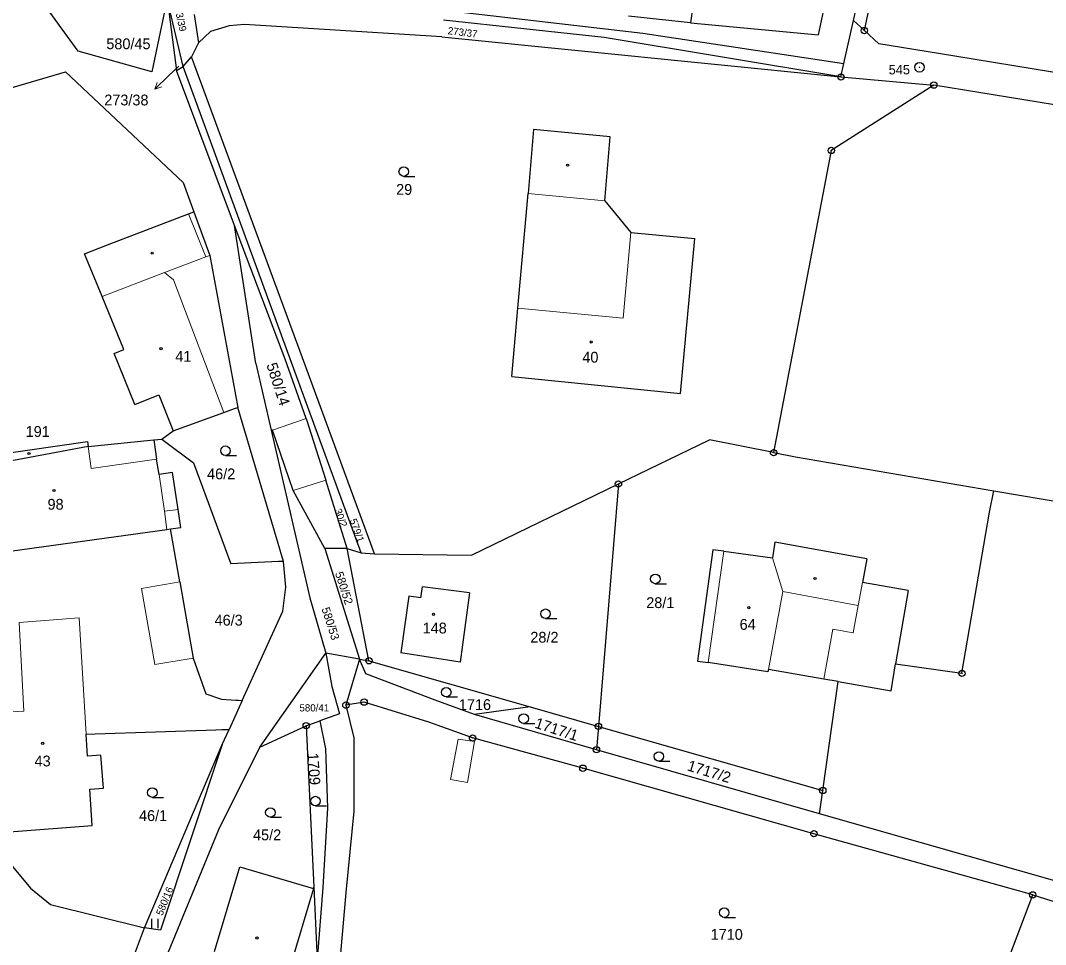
# Model space of a CAD drawing. Extents: x -601131 to -597152, y -1058536 to -1055911.
# Drawn here: x -599420.5 to -599259.4, y -1057423.7 to -1057278.4 of the extents above; entities that cross this region are included whole.
import ezdxf
from ezdxf.enums import TextEntityAlignment as Align

# ---------------------------------------------------------------- set-up
doc = ezdxf.new("R2010")
doc.units = 0
doc.header["$LTSCALE"] = 0.68
for name, color, linetype, lineweight in [('1', 7, 'Continuous', 25), ('3', 7, 'Continuous', 25), ('4', 7, 'Continuous', 13), ('5', 7, 'Continuous', 25), ('7', 7, 'Continuous', 13), ('8', 7, 'Continuous', 25)]:
    doc.layers.add(name, color=color, linetype=linetype, lineweight=lineweight)
doc.layers.add('2', color=7, linetype='Continuous')

msp = doc.modelspace()

# ---------------------------------------------------------------- linework, layer by layer
at = {"layer": '1'}
for p, q in [((-599289.57, -1057278.37), (-599276.24, -1057217.2)), ((-599309.65, -1057241.5), (-599315.21, -1057278.73)), ((-599295.06, -1057280.63), (-599287.53, -1057245.47)), ((-599287.86, -1057279.94), (-599281.16, -1057249.18)), ((-599411.44, -1057283.19), (-599419.47, -1057272.04)), ((-599397.46, -1057274.9), (-599399.88, -1057286.45)), ((-599394.93, -1057285.61), (-599397.46, -1057274.9)), ((-599397.46, -1057274.9), (-599395.98, -1057286.23)), ((-599393.21, -1057277.43), (-599392.54, -1057281.88)), ((-599353.84, -1057276.72), (-599322.66, -1057280.34)), ((-599385.29, -1057278.99), (-599387.72, -1057279.22)), ((-599354.25, -1057280.95), (-599385.29, -1057278.99)), ((-599328.78, -1057281.02), (-599353.99, -1057278.29)), ((-599315.21, -1057278.73), (-599324.94, -1057277.69)), ((-599315.21, -1057278.73), (-599295.06, -1057280.63)), ((-599291.08, -1057285.15), (-599289.57, -1057278.37)), ((-599287.86, -1057279.94), (-599289.57, -1057278.37)), ((-599390.63, -1057280.08), (-599392.54, -1057281.88)), ((-599387.72, -1057279.22), (-599390.63, -1057280.08)), ((-599322.66, -1057280.34), (-599291.08, -1057285.15)), ((-599285.6, -1057282.02), (-599287.86, -1057279.94)), ((-599392.54, -1057281.88), (-599393.64, -1057284.09)), ((-599354.25, -1057280.95), (-599291.54, -1057287.24)), ((-599291.54, -1057287.24), (-599328.78, -1057281.02)), ((-599276.23, -1057283.57), (-599285.6, -1057282.02)), ((-599399.88, -1057286.45), (-599411.44, -1057283.19)), ((-599251, -1057287.69), (-599276.23, -1057283.57)), ((-599395.98, -1057286.23), (-599394.93, -1057285.61)), ((-599394.93, -1057285.61), (-599393.64, -1057284.09)), ((-599366.95, -1057362.1), (-599394.93, -1057285.61)), ((-599375.82, -1057332.4), (-599393.64, -1057284.09)), ((-599291.54, -1057287.24), (-599291.08, -1057285.15)), ((-599425.53, -1057290.01), (-599413.41, -1057286.42)), ((-599413.41, -1057286.42), (-599394.93, -1057303.86)), ((-599386.84, -1057310.62), (-599395.98, -1057286.23)), ((-599291.54, -1057287.24), (-599276.95, -1057288.52)), ((-599276.95, -1057288.52), (-599293.06, -1057298.8)), ((-599241.43, -1057294.32), (-599276.95, -1057288.52)), ((-599339.85, -1057295.49), (-599340.72, -1057305.59)), ((-599327.81, -1057296.68), (-599339.85, -1057295.49)), ((-599328.67, -1057306.73), (-599327.81, -1057296.68)), ((-599293.06, -1057298.8), (-599302.13, -1057346.32)), ((-599394.93, -1057303.86), (-599393.26, -1057308.44)), ((-599342.34, -1057323.58), (-599340.72, -1057305.59)), ((-599328.67, -1057306.73), (-599324.55, -1057311.68)), ((-599406.81, -1057313.66), (-599394.07, -1057308.75)), ((-599394.07, -1057308.75), (-599393.26, -1057308.44)), ((-599393.26, -1057308.44), (-599390.76, -1057315.3)), ((-599378.9, -1057331.64), (-599386.84, -1057310.62)), ((-599383.52, -1057332.3), (-599386.84, -1057310.62)), ((-599324.55, -1057311.68), (-599314.52, -1057312.63)), ((-599316.77, -1057337.04), (-599314.52, -1057312.63)), ((-599410.42, -1057315.05), (-599406.81, -1057313.66)), ((-599407.67, -1057321.76), (-599410.42, -1057315.05)), ((-599390.76, -1057315.3), (-599386.33, -1057339.21)), ((-599404.27, -1057330.12), (-599407.67, -1057321.76)), ((-599343.29, -1057334.36), (-599342.34, -1057323.58)), ((-599405.78, -1057330.74), (-599404.27, -1057330.12)), ((-599402.52, -1057338.76), (-599405.78, -1057330.74)), ((-599383.52, -1057332.3), (-599381.1, -1057342.81)), ((-599375.62, -1057340.95), (-599378.9, -1057331.64)), ((-599364.88, -1057362.22), (-599375.82, -1057332.4)), ((-599343.29, -1057334.36), (-599316.77, -1057337.04)), ((-599402.52, -1057338.76), (-599398.77, -1057337.24)), ((-599398.77, -1057337.24), (-599396.48, -1057342.88)), ((-599396.48, -1057342.88), (-599388.55, -1057340.01)), ((-599388.55, -1057340.01), (-599386.87, -1057339.39)), ((-599386.87, -1057339.39), (-599386.33, -1057339.21)), ((-599379.14, -1057363.42), (-599386.33, -1057339.21)), ((-599375.62, -1057340.95), (-599372.49, -1057350.63)), ((-599398.26, -1057344.19), (-599396.48, -1057342.88)), ((-599380.9, -1057342.78), (-599381.1, -1057342.81)), ((-599381.1, -1057342.81), (-599375.04, -1057369.18)), ((-599377.65, -1057352.25), (-599380.9, -1057342.78)), ((-599425.85, -1057346.84), (-599409.99, -1057344.56)), ((-599409.99, -1057344.56), (-599409.88, -1057345.35)), ((-599409.88, -1057345.35), (-599399.55, -1057344.32)), ((-599399.55, -1057344.32), (-599398.26, -1057344.19)), ((-599399.55, -1057344.32), (-599399.11, -1057347.35)), ((-599398.26, -1057344.19), (-599393.33, -1057347.95)), ((-599326.52, -1057351.25), (-599312.23, -1057344.33)), ((-599302.13, -1057346.32), (-599312.23, -1057344.33)), ((-599409.88, -1057345.35), (-599425.64, -1057348.31)), ((-599302.13, -1057346.32), (-599298.7, -1057346.97)), ((-599398.71, -1057349.77), (-599399.11, -1057347.35)), ((-599393.33, -1057347.95), (-599387.43, -1057363.83)), ((-599298.7, -1057346.97), (-599267.5, -1057352.34)), ((-599396.59, -1057349.42), (-599398.71, -1057349.77)), ((-599395.7, -1057355.26), (-599396.59, -1057349.42)), ((-599369.18, -1057361.4), (-599372.49, -1057350.63)), ((-599349.59, -1057362.45), (-599326.52, -1057351.25)), ((-599326.52, -1057351.25), (-599329.66, -1057389.37)), ((-599372.68, -1057361.4), (-599377.65, -1057352.25)), ((-599268.21, -1057355.67), (-599267.5, -1057352.34)), ((-599267.5, -1057352.34), (-599196.38, -1057364.38)), ((-599395.29, -1057358.08), (-599395.7, -1057355.26)), ((-599272.52, -1057381.02), (-599268.21, -1057355.67)), ((-599396.94, -1057358.31), (-599395.29, -1057358.08)), ((-599423.64, -1057362.04), (-599397.5, -1057358.39)), ((-599397.5, -1057358.39), (-599396.94, -1057358.31)), ((-599395.47, -1057366.62), (-599396.94, -1057358.31)), ((-599301.96, -1057360.38), (-599302.3, -1057362.89)), ((-599287.49, -1057363.01), (-599301.96, -1057360.38)), ((-599369.18, -1057361.4), (-599372.68, -1057361.4)), ((-599365.73, -1057379.05), (-599369.18, -1057361.4)), ((-599369.18, -1057361.4), (-599366.95, -1057362.1)), ((-599366.95, -1057362.1), (-599364.88, -1057362.22)), ((-599364.88, -1057362.22), (-599349.59, -1057362.45)), ((-599311.68, -1057361.6), (-599314.09, -1057379.09)), ((-599309.95, -1057361.84), (-599311.68, -1057361.6)), ((-599309.95, -1057361.84), (-599302.3, -1057362.89)), ((-599379.93, -1057363.46), (-599387.43, -1057363.83)), ((-599379.14, -1057363.42), (-599379.93, -1057363.46)), ((-599378.8, -1057367.46), (-599379.14, -1057363.42)), ((-599287.49, -1057363.01), (-599288.17, -1057366.75)), ((-599395.47, -1057366.62), (-599393.34, -1057378.62)), ((-599379.24, -1057371.27), (-599378.8, -1057367.46)), ((-599357.55, -1057369.13), (-599357.33, -1057367.44)), ((-599349.92, -1057368.39), (-599357.33, -1057367.44)), ((-599280.98, -1057368), (-599288.17, -1057366.75)), ((-599375.04, -1057369.18), (-599372.49, -1057377.88)), ((-599359.48, -1057368.87), (-599360.7, -1057377.83)), ((-599357.55, -1057369.13), (-599359.48, -1057368.87)), ((-599349.92, -1057368.39), (-599351.41, -1057379.27)), ((-599280.98, -1057368), (-599282.95, -1057379.52)), ((-599385.64, -1057385.31), (-599379.24, -1057371.27)), ((-599393.34, -1057378.62), (-599391.38, -1057384.25)), ((-599382.87, -1057392.64), (-599372.49, -1057377.88)), ((-599367.24, -1057378.79), (-599372.49, -1057377.88)), ((-599372.49, -1057377.88), (-599371.54, -1057383.11)), ((-599367.24, -1057378.79), (-599369.35, -1057386.03)), ((-599366.21, -1057381.11), (-599367.24, -1057378.79)), ((-599365.73, -1057379.05), (-599340.38, -1057386.3)), ((-599351.41, -1057379.27), (-599360.7, -1057377.83)), ((-599314.09, -1057379.09), (-599312.39, -1057379.35)), ((-599303.02, -1057380.77), (-599312.39, -1057379.35)), ((-599302.95, -1057380.4), (-599303.02, -1057380.77)), ((-599294.24, -1057381.92), (-599302.95, -1057380.4)), ((-599283.65, -1057383.76), (-599282.95, -1057379.52)), ((-599282.95, -1057379.52), (-599272.52, -1057381.02)), ((-599355.31, -1057385.24), (-599366.21, -1057381.11)), ((-599292, -1057382.32), (-599294.24, -1057381.92)), ((-599371.54, -1057383.11), (-599370.34, -1057387.38)), ((-599294.4, -1057399.45), (-599292, -1057382.32)), ((-599292, -1057382.32), (-599283.65, -1057383.76)), ((-599391.38, -1057384.25), (-599388.93, -1057385.08)), ((-599388.93, -1057385.08), (-599386.67, -1057385.24)), ((-599385.64, -1057385.31), (-599387.7, -1057389.84)), ((-599386.67, -1057385.24), (-599386.25, -1057385.27)), ((-599386.25, -1057385.27), (-599385.64, -1057385.31)), ((-599349.16, -1057387.51), (-599355.31, -1057385.24)), ((-599366.49, -1057385.56), (-599369.35, -1057386.03)), ((-599369.35, -1057386.03), (-599368.11, -1057391.18)), ((-599356.3, -1057388.72), (-599366.49, -1057385.56)), ((-599340.38, -1057386.3), (-599349.16, -1057387.51)), ((-599340.38, -1057386.3), (-599329.66, -1057389.37)), ((-599375.59, -1057389.26), (-599373.46, -1057388.5)), ((-599370.34, -1057387.38), (-599373.46, -1057388.5)), ((-599373.46, -1057388.5), (-599372.57, -1057392.88)), ((-599349.44, -1057391.19), (-599356.3, -1057388.72)), ((-599329.97, -1057393.04), (-599349.16, -1057387.51)), ((-599408.76, -1057390.52), (-599389.82, -1057389.91)), ((-599389.82, -1057389.91), (-599388.82, -1057389.88)), ((-599388.82, -1057389.88), (-599387.7, -1057389.84)), ((-599388.79, -1057392.24), (-599387.7, -1057389.84)), ((-599382.87, -1057392.64), (-599375.59, -1057389.26)), ((-599375.59, -1057389.26), (-599374.41, -1057414.64)), ((-599329.66, -1057389.37), (-599329.97, -1057393.04)), ((-599329.66, -1057389.37), (-599294.4, -1057399.45)), ((-599410.19, -1057390.57), (-599408.76, -1057390.52)), ((-599409.98, -1057394.05), (-599410.19, -1057390.57)), ((-599368.11, -1057391.18), (-599368.13, -1057402.69)), ((-599332.11, -1057395.95), (-599349.44, -1057391.19)), ((-599400.99, -1057421.07), (-599388.79, -1057392.24)), ((-599388.79, -1057392.24), (-599398.51, -1057421.4)), ((-599389.32, -1057405.57), (-599382.87, -1057392.64)), ((-599372.57, -1057392.88), (-599372.26, -1057402.22)), ((-599294.92, -1057403.13), (-599329.97, -1057393.04)), ((-599407.86, -1057393.92), (-599409.98, -1057394.05)), ((-599407.45, -1057399.09), (-599407.86, -1057393.92)), ((-599295.79, -1057406.25), (-599332.11, -1057395.95)), ((-599409.61, -1057399.24), (-599407.45, -1057399.09)), ((-599409.22, -1057404.94), (-599409.61, -1057399.24)), ((-599294.92, -1057403.13), (-599294.4, -1057399.45)), ((-599372.26, -1057402.22), (-599373, -1057414.71)), ((-599368.13, -1057402.69), (-599369.37, -1057415.48)), ((-599236.7, -1057419.73), (-599294.92, -1057403.13)), ((-599427.99, -1057403.92), (-599418.95, -1057414.8)), ((-599422.24, -1057405.98), (-599409.22, -1057404.94)), ((-599397.22, -1057424.81), (-599389.32, -1057405.57)), ((-599261.4, -1057415.87), (-599295.79, -1057406.25)), ((-599389.98, -1057424.78), (-599386.04, -1057411.48)), ((-599386.04, -1057411.48), (-599374.47, -1057414.85)), ((-599418.95, -1057414.8), (-599415.76, -1057417.37)), ((-599374.47, -1057414.85), (-599380.85, -1057436.39)), ((-599374.47, -1057414.85), (-599374.41, -1057414.64)), ((-599374.41, -1057414.64), (-599373.88, -1057426.01)), ((-599373, -1057414.71), (-599373.88, -1057426.01)), ((-599369.37, -1057415.48), (-599370.18, -1057425.11)), ((-599274.58, -1057450.67), (-599261.4, -1057415.87)), ((-599261.4, -1057415.87), (-599237.59, -1057423.29)), ((-599415.76, -1057417.37), (-599400.99, -1057421.07)), ((-599408.91, -1057441.67), (-599400.99, -1057421.07)), ((-599398.51, -1057421.4), (-599400.99, -1057421.07))]:
    msp.add_line(p, q, dxfattribs=at)
msp.add_lwpolyline([(-599372.68, -1057361.4), (-599367.24, -1057378.79), (-599365.73, -1057379.05)], dxfattribs=at)
at = {"layer": '3'}
for p, q in [((-599360.263, -1057302.87), (-599358.513, -1057302.87)), ((-599388.283, -1057346.77), (-599386.533, -1057346.77)), ((-599320.723, -1057366.93), (-599318.973, -1057366.93)), ((-599337.973, -1057372.41), (-599336.223, -1057372.41)), ((-599353.583, -1057384.75), (-599351.833, -1057384.75)), ((-599341.413, -1057388.9), (-599339.663, -1057388.9)), ((-599320.163, -1057394.85), (-599318.413, -1057394.85)), ((-599399.773, -1057400.53), (-599398.023, -1057400.53)), ((-599374.143, -1057401.87), (-599372.393, -1057401.87)), ((-599381.223, -1057403.67), (-599379.473, -1057403.67)), ((-599399.881, -1057421.12), (-599399.881, -1057419.62)), ((-599398.88, -1057421.12), (-599398.88, -1057419.62)), ((-599309.893, -1057419.41), (-599308.143, -1057419.41))]:
    msp.add_line(p, q, dxfattribs=at)
for centre in [(-599360.2629, -1057302.1198), (-599388.2829, -1057346.0198), (-599320.7229, -1057366.1798), (-599337.9729, -1057371.6598), (-599353.5829, -1057383.9998), (-599341.4129, -1057388.1498), (-599320.1629, -1057394.0998), (-599399.7729, -1057399.7798), (-599374.1429, -1057401.1198), (-599381.2229, -1057402.9198), (-599309.8929, -1057418.6598)]:
    msp.add_circle(centre, 0.75, dxfattribs=at)
at = {"layer": '4'}
for p, q in [((-599340.72, -1057305.59), (-599328.67, -1057306.73)), ((-599391.36, -1057315.52), (-599394.07, -1057308.75)), ((-599324.55, -1057311.68), (-599325.79, -1057325.19)), ((-599397.84, -1057317.97), (-599391.36, -1057315.52)), ((-599391.36, -1057315.52), (-599390.76, -1057315.3)), ((-599397.84, -1057317.97), (-599407.67, -1057321.76)), ((-599396.47, -1057319.15), (-599397.84, -1057317.97)), ((-599396.47, -1057319.15), (-599388.55, -1057340.01)), ((-599342.34, -1057323.58), (-599325.79, -1057325.19)), ((-599380.9, -1057342.78), (-599375.62, -1057340.95)), ((-599409.88, -1057345.35), (-599409.38, -1057348.81)), ((-599399.11, -1057347.35), (-599409.38, -1057348.81)), ((-599397.88, -1057355.55), (-599398.71, -1057349.77)), ((-599372.49, -1057350.63), (-599377.65, -1057352.25)), ((-599397.88, -1057355.55), (-599395.7, -1057355.26)), ((-599397.5, -1057358.39), (-599397.88, -1057355.55)), ((-599312.39, -1057379.35), (-599309.95, -1057361.84)), ((-599302.3, -1057362.89), (-599300.68, -1057368.14)), ((-599395.47, -1057366.62), (-599401.49, -1057367.67)), ((-599401.49, -1057367.67), (-599399.41, -1057379.66)), ((-599288.17, -1057366.75), (-599288.82, -1057370.34)), ((-599302.95, -1057380.4), (-599300.68, -1057368.14)), ((-599300.68, -1057368.14), (-599288.82, -1057370.34)), ((-599289.6, -1057374.64), (-599288.82, -1057370.34)), ((-599420.72, -1057373.02), (-599411.3, -1057372.3)), ((-599411.3, -1057372.3), (-599410.19, -1057390.57)), ((-599420.72, -1057373.02), (-599419.97, -1057386.97)), ((-599294.24, -1057381.92), (-599292.83, -1057374.06)), ((-599292.83, -1057374.06), (-599289.6, -1057374.64)), ((-599399.41, -1057379.66), (-599393.34, -1057378.62)), ((-599419.97, -1057386.97), (-599423.75, -1057387.17)), ((-599351.72, -1057391.37), (-599352.91, -1057397.74)), ((-599349.12, -1057391.75), (-599351.72, -1057391.37)), ((-599350.23, -1057398.21), (-599349.12, -1057391.75)), ((-599352.91, -1057397.74), (-599350.23, -1057398.21))]:
    msp.add_line(p, q, dxfattribs=at)
at = {"layer": '5'}
for centre in [(-599334.4968, -1057301.1192), (-599399.8068, -1057314.9492), (-599330.8068, -1057328.9092), (-599398.4068, -1057329.9592), (-599419.1568, -1057346.4592), (-599415.2468, -1057352.2692), (-599295.6168, -1057366.1192), (-599306.0268, -1057370.6992), (-599355.5868, -1057371.7592), (-599416.9968, -1057392.0192), (-599383.3268, -1057422.6592)]:
    msp.add_circle(centre, 0.175, dxfattribs=at)
at = {"layer": '7'}
msp.add_line((-599399.379, -1057289.145), (-599398.31, -1057288.809), dxfattribs=at)
msp.add_lwpolyline([(-599395.63, -1057285.52), (-599397.22, -1057287.06), (-599399.379, -1057289.145), (-599399.006, -1057288.089)], dxfattribs=at)
at = {"layer": '8'}
for centre, radius in [((-599287.86, -1057279.9399), 0.5), ((-599287.86, -1057279.9399), 0.0303), ((-599279.2, -1057285.7198), 0.75), ((-599291.54, -1057287.2399), 0.5), ((-599291.54, -1057287.2399), 0.0303), ((-599279.2, -1057285.7198), 0.03), ((-599276.95, -1057288.5199), 0.5), ((-599276.95, -1057288.5199), 0.0303), ((-599293.06, -1057298.7999), 0.5), ((-599293.06, -1057298.7999), 0.0303), ((-599302.13, -1057346.3199), 0.5), ((-599302.13, -1057346.3199), 0.0303), ((-599326.52, -1057351.2499), 0.5), ((-599326.52, -1057351.2499), 0.0303), ((-599365.73, -1057379.0499), 0.5), ((-599365.73, -1057379.0499), 0.0303), ((-599272.52, -1057381.0199), 0.5), ((-599272.52, -1057381.0199), 0.0303), ((-599366.49, -1057385.5599), 0.5), ((-599369.35, -1057386.0299), 0.5), ((-599369.35, -1057386.0299), 0.0303), ((-599366.49, -1057385.5599), 0.0303), ((-599375.59, -1057389.2599), 0.5), ((-599375.59, -1057389.2599), 0.0303), ((-599329.66, -1057389.3699), 0.5), ((-599329.66, -1057389.3699), 0.0303), ((-599349.44, -1057391.1899), 0.5), ((-599349.44, -1057391.1899), 0.0303), ((-599329.97, -1057393.0399), 0.5), ((-599329.97, -1057393.0399), 0.0303), ((-599332.11, -1057395.9499), 0.5), ((-599332.11, -1057395.9499), 0.0303), ((-599294.4, -1057399.4499), 0.5), ((-599294.4, -1057399.4499), 0.0303), ((-599295.79, -1057406.2499), 0.5), ((-599295.79, -1057406.2499), 0.0303), ((-599261.4, -1057415.8699), 0.5), ((-599261.4, -1057415.8699), 0.0303)]:
    msp.add_circle(centre, radius, dxfattribs=at)

# ---------------------------------------------------------------- texts
at = {"layer": '2'}
for s, height, rotation, p in [('273/39', 1.14, 282, (-599396.458, -1057275.599)), ('273/37', 1.14, 353, (-599353.384, -1057280.502)), ('580/14', 1.7, 288, (-599381.874, -1057332.501)), ('30/2', 1.14, 290, (-599371.177, -1057355.377)), ('579/1', 1.14, 290, (-599368.787, -1057356.947)), ('580/16', 1.14, 68, (-599398.195, -1057419.216))]:
    msp.add_text(s, height=height, rotation=rotation, dxfattribs=at).set_placement(p)
for s, height, p in [('580/45', 1.7, (-599407.01, -1057282.875)), ('29', 1.7, (-599361.46, -1057305.775)), ('41', 1.7, (-599396.17, -1057332.025)), ('40', 1.7, (-599332.19, -1057332.165)), ('191', 1.7, (-599419.69, -1057343.844)), ('46/2', 1.7, (-599391.17, -1057350.515)), ('98', 1.7, (-599416.25, -1057355.295)), ('28/1', 1.7, (-599322.15, -1057370.765)), ('46/3', 1.7, (-599389.99, -1057373.515)), ('64', 1.7, (-599307.47, -1057374.185)), ('148', 1.7, (-599357.29, -1057374.755)), ('28/2', 1.7, (-599340.36, -1057376.205)), ('580/41', 1.14, (-599376.65, -1057387.025)), ('43', 1.7, (-599418.29, -1057395.665)), ('46/1', 1.7, (-599401.87, -1057404.255)), ('45/2', 1.7, (-599383.95, -1057407.285))]:
    msp.add_text(s, height=height, dxfattribs=at).set_placement(p)
msp.add_text('273/38', height=1.7, dxfattribs=at).set_placement((-599400.379, -1057291.715), align=Align.RIGHT)
for s, height, rotation, p in [('580/52', 1.3, 288, (-599370.2657, -1057367.8121)), ('580/53', 1.3, 288, (-599372.3757, -1057373.4021)), ('1717/1', 1.7, 342, (-599336.4877, -1057390.6276)), ('1709', 1.7, 274, (-599375.217, -1057396.1297)), ('1717/2', 1.7, 343, (-599312.4975, -1057397.2842))]:
    msp.add_text(s, height=height, rotation=rotation, dxfattribs=at).set_placement(p, align=Align.CENTER)
for s, p in [('1716', (-599349.07, -1057386.802)), ('1710', (-599309.5, -1057422.932))]:
    msp.add_text(s, height=1.7, dxfattribs=at).set_placement(p, align=Align.CENTER)
at = {"layer": '8'}
msp.add_text('545', height=1.5, dxfattribs=at).set_placement((-599280.699, -1057286.837), align=Align.RIGHT)

doc.saveas('drawing.dxf')
